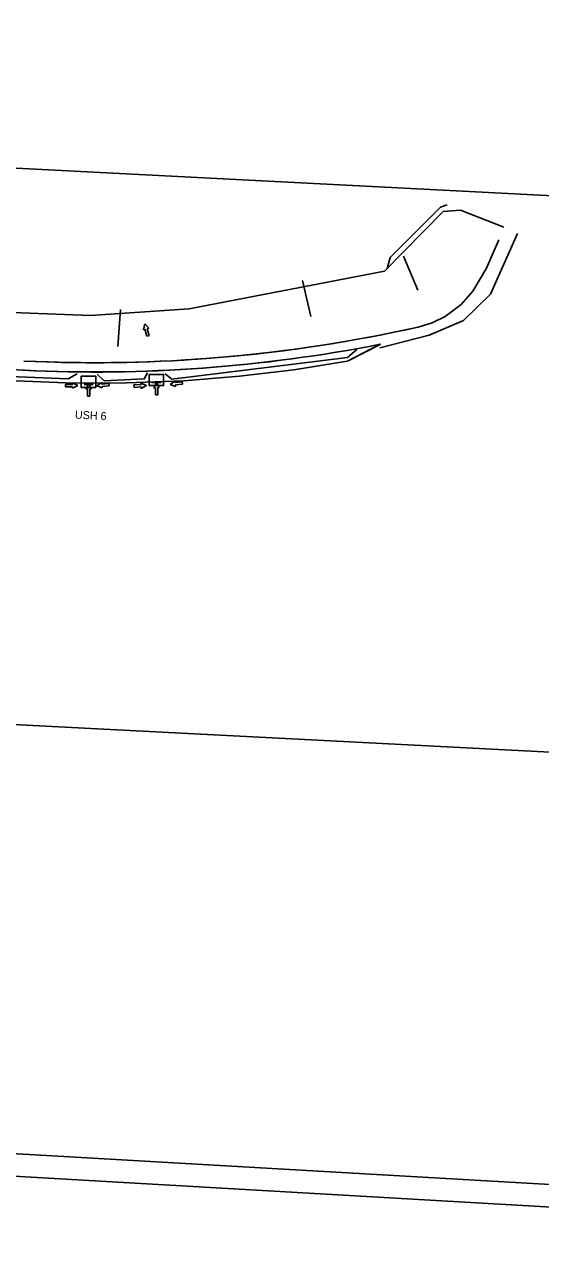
# Model space of a CAD drawing. Extents: x 20499990 to 20505779, y 7953198 to 7954399.
# Drawn here: x 20505029 to 20505308, y 7953198 to 7953862 of the extents above; entities that cross this region are included whole.
import ezdxf

# ---------------------------------------------------------------- set-up
doc = ezdxf.new("R2010")
doc.units = 0
for name, color, linetype in [('Building', 7, 'Continuous'), ('Draft_DNC', 7, 'Continuous'), ('dsnCellElements', 7, 'Continuous'), ('ErosionControl', 7, 'Continuous'), ('NamedBoundary', 7, 'Continuous'), ('Seeding', 7, 'Continuous'), ('Text', 7, 'Continuous')]:
    doc.layers.add(name, color=color, linetype=linetype)

msp = doc.modelspace()

# ---------------------------------------------------------------- linework, layer by layer
at = {"layer": 'Building'}
for p, q in [((20505287.85, 7953752.16), (20505264.52, 7953761.4)), ((20504707.68, 7953690.4), (20505029.34, 7953674.9)), ((20505221.15, 7953688.97), (20505221.15, 7953688.97))]:
    msp.add_line(p, q, dxfattribs=at)
for points in [[(20505264.52, 7953761.4), (20505255.15, 7953760.64), (20505223.48, 7953728.42), (20505118.14, 7953708.13), (20505064.87, 7953704.49), (20504915.31, 7953710.24), (20504866.73, 7953716.98), (20504755.09, 7953722.82), (20504744.66, 7953721.51), (20504646.98, 7953723.97), (20504555.07, 7953724.24)], [(20505225.3, 7953694.78), (20505237.3, 7953697.29), (20505241.76, 7953698.28), (20505249.25, 7953700.58), (20505256.29, 7953704.03), (20505264.83, 7953710.4), (20505271.21, 7953717.57), (20505278.49, 7953729.98), (20505285.29, 7953745.35)], [(20505221.15, 7953688.97), (20505203.52, 7953679.84)], [(20505061.3, 7953667.91), (20505051.67, 7953668.07), (20505024.81, 7953669.14), (20505009.01, 7953669.85), (20504973.68, 7953671.52), (20504935.49, 7953673.34), (20504898.88, 7953675.21), (20504861.14, 7953676.98), (20504823.16, 7953678.8), (20504783.91, 7953680.73), (20504745.3, 7953682.65), (20504710.5, 7953684.26), (20504707.21, 7953684.41)], [(20505203.46, 7953679.8), (20505174.64, 7953675.19), (20505145.29, 7953671.75), (20505115.23, 7953669.27), (20505084.35, 7953668.13), (20505061.3, 7953667.91)]]:
    msp.add_lwpolyline(points, dxfattribs=at)
for centre, radius, start, end in [((20505067.33, 7954478), 799, 267.24196, 281.40324), ((20505067.56, 7954468.39), 794.41, 267.24197, 281.14725), ((20505221.16, 7953688.91), 0.06, 347.65521, 101.14725)]:
    msp.add_arc(centre, radius, start, end, dxfattribs=at)
at = {"layer": 'Draft_DNC'}
for points in [[(20502378.98, 7953404.37), (20502465.54, 7954399.08), (20505611.36, 7954341.07), (20505615.95, 7953217.82)], [(20502519.96, 7953384.14), (20502606.52, 7954378.84), (20505752.34, 7954320.84), (20505756.93, 7953197.59)]]:
    msp.add_lwpolyline(points, close=True, dxfattribs=at)
at = {"layer": 'dsnCellElements'}
for p, q in [((20505093.53, 7953696.81), (20505094.12, 7953699.95)), ((20505094.12, 7953699.95), (20505096.28, 7953697.6)), ((20505094.29, 7953697.03), (20505093.53, 7953696.81)), ((20505095.35, 7953693.36), (20505094.29, 7953697.03)), ((20505096.57, 7953693.71), (20505095.35, 7953693.36)), ((20505096.28, 7953697.6), (20505095.52, 7953697.38)), ((20505095.52, 7953697.38), (20505096.57, 7953693.71)), ((20505051.37, 7953667.29), (20505055.18, 7953667.33)), ((20505051.37, 7953667.29), (20505055.18, 7953667.33)), ((20505051.38, 7953666.02), (20505051.37, 7953667.29)), ((20505051.38, 7953666.02), (20505051.37, 7953667.29)), ((20505055.17, 7953668.13), (20505058.05, 7953666.73)), ((20505055.18, 7953667.33), (20505055.17, 7953668.13)), ((20505055.17, 7953668.13), (20505058.05, 7953666.73)), ((20505055.18, 7953667.33), (20505055.17, 7953668.13)), ((20505058.05, 7953666.73), (20505055.21, 7953665.26)), ((20505058.05, 7953666.73), (20505055.21, 7953665.26)), ((20505062.44, 7953664.83), (20505063.91, 7953667.68)), ((20505062.44, 7953664.83), (20505063.91, 7953667.68)), ((20505063.91, 7953667.68), (20505065.31, 7953664.8)), ((20505063.91, 7953667.68), (20505065.31, 7953664.8)), ((20505068.22, 7953666.53), (20505070.93, 7953668.24)), ((20505068.22, 7953666.53), (20505070.93, 7953668.24)), ((20505071.21, 7953665.39), (20505068.22, 7953666.53)), ((20505071.21, 7953665.39), (20505068.22, 7953666.53)), ((20505070.93, 7953668.24), (20505071, 7953667.45)), ((20505070.93, 7953668.24), (20505071, 7953667.45)), ((20505071, 7953667.45), (20505074.8, 7953667.83)), ((20505071, 7953667.45), (20505074.8, 7953667.83)), ((20505074.93, 7953666.56), (20505071.13, 7953666.19)), ((20505074.93, 7953666.56), (20505071.13, 7953666.19)), ((20505071.13, 7953666.19), (20505071.21, 7953665.39)), ((20505071.13, 7953666.19), (20505071.21, 7953665.39)), ((20505074.8, 7953667.83), (20505074.93, 7953666.56)), ((20505074.8, 7953667.83), (20505074.93, 7953666.56)), ((20505088.35, 7953666.98), (20505092.16, 7953667.23)), ((20505088.35, 7953666.98), (20505092.16, 7953667.23)), ((20505088.43, 7953665.71), (20505088.35, 7953666.98)), ((20505088.43, 7953665.71), (20505088.35, 7953666.98)), ((20505092.11, 7953668.02), (20505095.06, 7953666.78)), ((20505092.16, 7953667.23), (20505092.11, 7953668.02)), ((20505092.11, 7953668.02), (20505095.06, 7953666.78)), ((20505092.16, 7953667.23), (20505092.11, 7953668.02)), ((20505095.06, 7953666.78), (20505092.29, 7953665.17)), ((20505095.06, 7953666.78), (20505092.29, 7953665.17)), ((20505099.12, 7953665.49), (20505100.46, 7953668.39)), ((20505099.12, 7953665.49), (20505100.46, 7953668.39)), ((20505100.46, 7953668.39), (20505101.98, 7953665.58)), ((20505100.46, 7953668.39), (20505101.98, 7953665.58)), ((20505107.79, 7953667.28), (20505110.46, 7953669.04)), ((20505107.79, 7953667.28), (20505110.46, 7953669.04)), ((20505110.8, 7953666.2), (20505107.79, 7953667.28)), ((20505110.8, 7953666.2), (20505107.79, 7953667.28)), ((20505110.46, 7953669.04), (20505110.55, 7953668.25)), ((20505110.46, 7953669.04), (20505110.55, 7953668.25)), ((20505110.55, 7953668.25), (20505114.34, 7953668.7)), ((20505110.55, 7953668.25), (20505114.34, 7953668.7)), ((20505114.49, 7953667.44), (20505110.7, 7953666.98)), ((20505114.49, 7953667.44), (20505110.7, 7953666.98)), ((20505110.7, 7953666.98), (20505110.8, 7953666.2)), ((20505110.7, 7953666.98), (20505110.8, 7953666.2)), ((20505114.34, 7953668.7), (20505114.49, 7953667.44)), ((20505114.34, 7953668.7), (20505114.49, 7953667.44)), ((20505055.2, 7953666.06), (20505051.38, 7953666.02)), ((20505055.2, 7953666.06), (20505051.38, 7953666.02)), ((20505055.21, 7953665.26), (20505055.2, 7953666.06)), ((20505055.21, 7953665.26), (20505055.2, 7953666.06)), ((20505063.24, 7953664.82), (20505062.44, 7953664.83)), ((20505063.24, 7953664.82), (20505062.44, 7953664.83)), ((20505063.2, 7953661.01), (20505063.24, 7953664.82)), ((20505063.2, 7953661.01), (20505063.24, 7953664.82)), ((20505064.47, 7953660.99), (20505063.2, 7953661.01)), ((20505064.47, 7953660.99), (20505063.2, 7953661.01)), ((20505064.51, 7953664.81), (20505064.47, 7953660.99)), ((20505064.51, 7953664.81), (20505064.47, 7953660.99)), ((20505065.31, 7953664.8), (20505064.51, 7953664.81)), ((20505065.31, 7953664.8), (20505064.51, 7953664.81)), ((20505092.24, 7953665.96), (20505088.43, 7953665.71)), ((20505092.24, 7953665.96), (20505088.43, 7953665.71)), ((20505092.29, 7953665.17), (20505092.24, 7953665.96)), ((20505092.29, 7953665.17), (20505092.24, 7953665.96)), ((20505099.92, 7953665.51), (20505099.12, 7953665.49)), ((20505099.92, 7953665.51), (20505099.12, 7953665.49)), ((20505100.03, 7953661.7), (20505099.92, 7953665.51)), ((20505100.03, 7953661.7), (20505099.92, 7953665.51)), ((20505101.31, 7953661.74), (20505100.03, 7953661.7)), ((20505101.31, 7953661.74), (20505100.03, 7953661.7)), ((20505101.98, 7953665.58), (20505101.19, 7953665.55)), ((20505101.98, 7953665.58), (20505101.19, 7953665.55)), ((20505101.19, 7953665.55), (20505101.31, 7953661.74)), ((20505101.19, 7953665.55), (20505101.31, 7953661.74))]:
    msp.add_line(p, q, dxfattribs=at)
at = {"layer": 'ErosionControl'}
for p, q in [((20505241.51, 7953718.13), (20505233.73, 7953736.56)), ((20505183.8, 7953703.93), (20505179.36, 7953723.43)), ((20505079.71, 7953687.74), (20505081, 7953707.7)), ((20505066.39, 7953667.27), (20505061.39, 7953667.29)), ((20505103.01, 7953668.25), (20505098.01, 7953668.27))]:
    msp.add_line(p, q, dxfattribs=at)
for points in [[(20505257.29, 7953764.32), (20505253.72, 7953763.03), (20505226.66, 7953735.83), (20505224.94, 7953729.67)], [(20505220.96, 7953687.05), (20505247.61, 7953693.83), (20505266.12, 7953701.8), (20505280.68, 7953716), (20505295.33, 7953748.7)], [(20505105.26, 7953672.99), (20505108.83, 7953670.15), (20505203.48, 7953681.79), (20505208.63, 7953686.08)], [(20504945.21, 7953677.32), (20504949.23, 7953674.41), (20505052.79, 7953670.38), (20505057.71, 7953673.07)], [(20505068.53, 7953672.81), (20505072.19, 7953669.23), (20505093.9, 7953670.24), (20505095.64, 7953673.54)]]:
    msp.add_lwpolyline(points, dxfattribs=at)
for points in [[(20505059.85, 7953671.74), (20505067.71, 7953671.74), (20505067.71, 7953665.67), (20505059.85, 7953665.67)], [(20505096.47, 7953672.72), (20505104.33, 7953672.72), (20505104.33, 7953666.65), (20505096.47, 7953666.65)]]:
    msp.add_lwpolyline(points, close=True, dxfattribs=at)
at = {"layer": 'NamedBoundary'}
msp.add_lwpolyline([(20504839.57, 7953793.6), (20504824.13, 7953494), (20505763.38, 7953445.57), (20505778.83, 7953745.18)], close=True, dxfattribs=at)
at = {"layer": 'Seeding'}
for p, q in [((20505287.85, 7953752.16), (20505264.52, 7953761.4)), ((20505221.13, 7953688.85), (20505221.13, 7953688.85))]:
    msp.add_line(p, q, dxfattribs=at)
for points in [[(20505264.52, 7953761.4), (20505255.15, 7953760.64), (20505223.48, 7953728.42), (20505118.14, 7953708.13), (20505064.87, 7953704.49), (20504915.31, 7953710.24), (20504866.73, 7953716.98), (20504755.09, 7953722.82), (20504744.66, 7953721.51), (20504646.98, 7953723.97), (20504555.07, 7953724.24)], [(20505241.76, 7953698.28), (20505249.25, 7953700.58), (20505256.29, 7953704.03), (20505264.83, 7953710.4), (20505271.21, 7953717.57), (20505278.49, 7953729.98), (20505285.29, 7953745.35)], [(20505221.13, 7953688.85), (20505203.52, 7953679.84)], [(20505061.3, 7953667.91), (20505051.67, 7953668.07), (20505024.81, 7953669.14), (20505009.01, 7953669.85), (20504973.68, 7953671.52), (20504935.49, 7953673.34), (20504898.88, 7953675.21), (20504861.14, 7953676.98), (20504823.16, 7953678.8), (20504783.91, 7953680.73), (20504745.3, 7953682.65), (20504710.5, 7953684.26), (20504707.21, 7953684.41)], [(20505203.46, 7953679.8), (20505174.64, 7953675.19), (20505145.29, 7953671.75), (20505115.23, 7953669.27), (20505084.35, 7953668.13), (20505061.3, 7953667.91)]]:
    msp.add_lwpolyline(points, dxfattribs=at)
for centre, radius, start, end in [((20505067.33, 7954478), 799, 267.24196, 282.60964), ((20505067.14, 7954474.15), 800.15, 267.24197, 281.0968), ((20505221.16, 7953688.91), 0.0624, 243.20417, 101.0968)]:
    msp.add_arc(centre, radius, start, end, dxfattribs=at)

# ---------------------------------------------------------------- texts
at = {"layer": 'Text'}
msp.add_text('USH 6', height=4.32, rotation=356.90003, dxfattribs=at).set_placement((20505056.42, 7953648.87))

doc.saveas('drawing.dxf')
